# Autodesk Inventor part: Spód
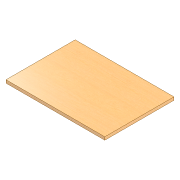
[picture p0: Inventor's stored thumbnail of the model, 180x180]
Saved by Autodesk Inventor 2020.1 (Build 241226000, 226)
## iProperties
Created: 2005-09
Part Number: Spód
Document SubType Name: Modeling
Designer: F.Stasiak
Density: 1 g/cm^3
Material: Ogólny
Appearance: Sosna żółta — pełna — barwiona na jasno — niski połysk
Manager: www.cadconsulting.pl
Company: Fabian Stasiak CAD Consulting
Author: F.Stasiak
Subject: Zbiór ćwiczeń. Autodesk Inventor 2020. Kurs podstawowy
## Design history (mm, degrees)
sketch "Szkic2"
  geometry: L1 (250, -175)-(-250, -175); L2 (-250, -175)-(-250, 175); L3 (-250, 175)-(250, 175); L4 (250, 175)-(250, -175); L5 (250, -175)-(-250, 175); L6 (-250, -175)-(250, 175); 1 further point
  constraints: 12 end point, 2 midpoint, 2 parallel, 1 horizontal, 1 perpendicular
  dimensions: "d4" = 500 distance of L2.end L3.end; "d5" = 350 distance of L1.end L2.end
extrude "Wyciągnięcie proste2" new body sketch "Szkic2" distance "d6" = 15; taper "d7" = 0 deg
node "Bryła2"
node "Korpusy bryłowe"
node "Korpusy powierzchniowe"
